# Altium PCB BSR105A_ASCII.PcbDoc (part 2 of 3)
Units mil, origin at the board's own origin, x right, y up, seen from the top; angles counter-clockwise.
Board outline 4010.03 x 4016.63 mil, 6 copper layers (Top Layer, Mid-Layer 1, Mid-Layer 2, Mid-Layer 3, Mid-Layer 4, Bottom Layer), stack 61.2 mil thick; 167 components, 58 nets, 398 pads, 190 vias.
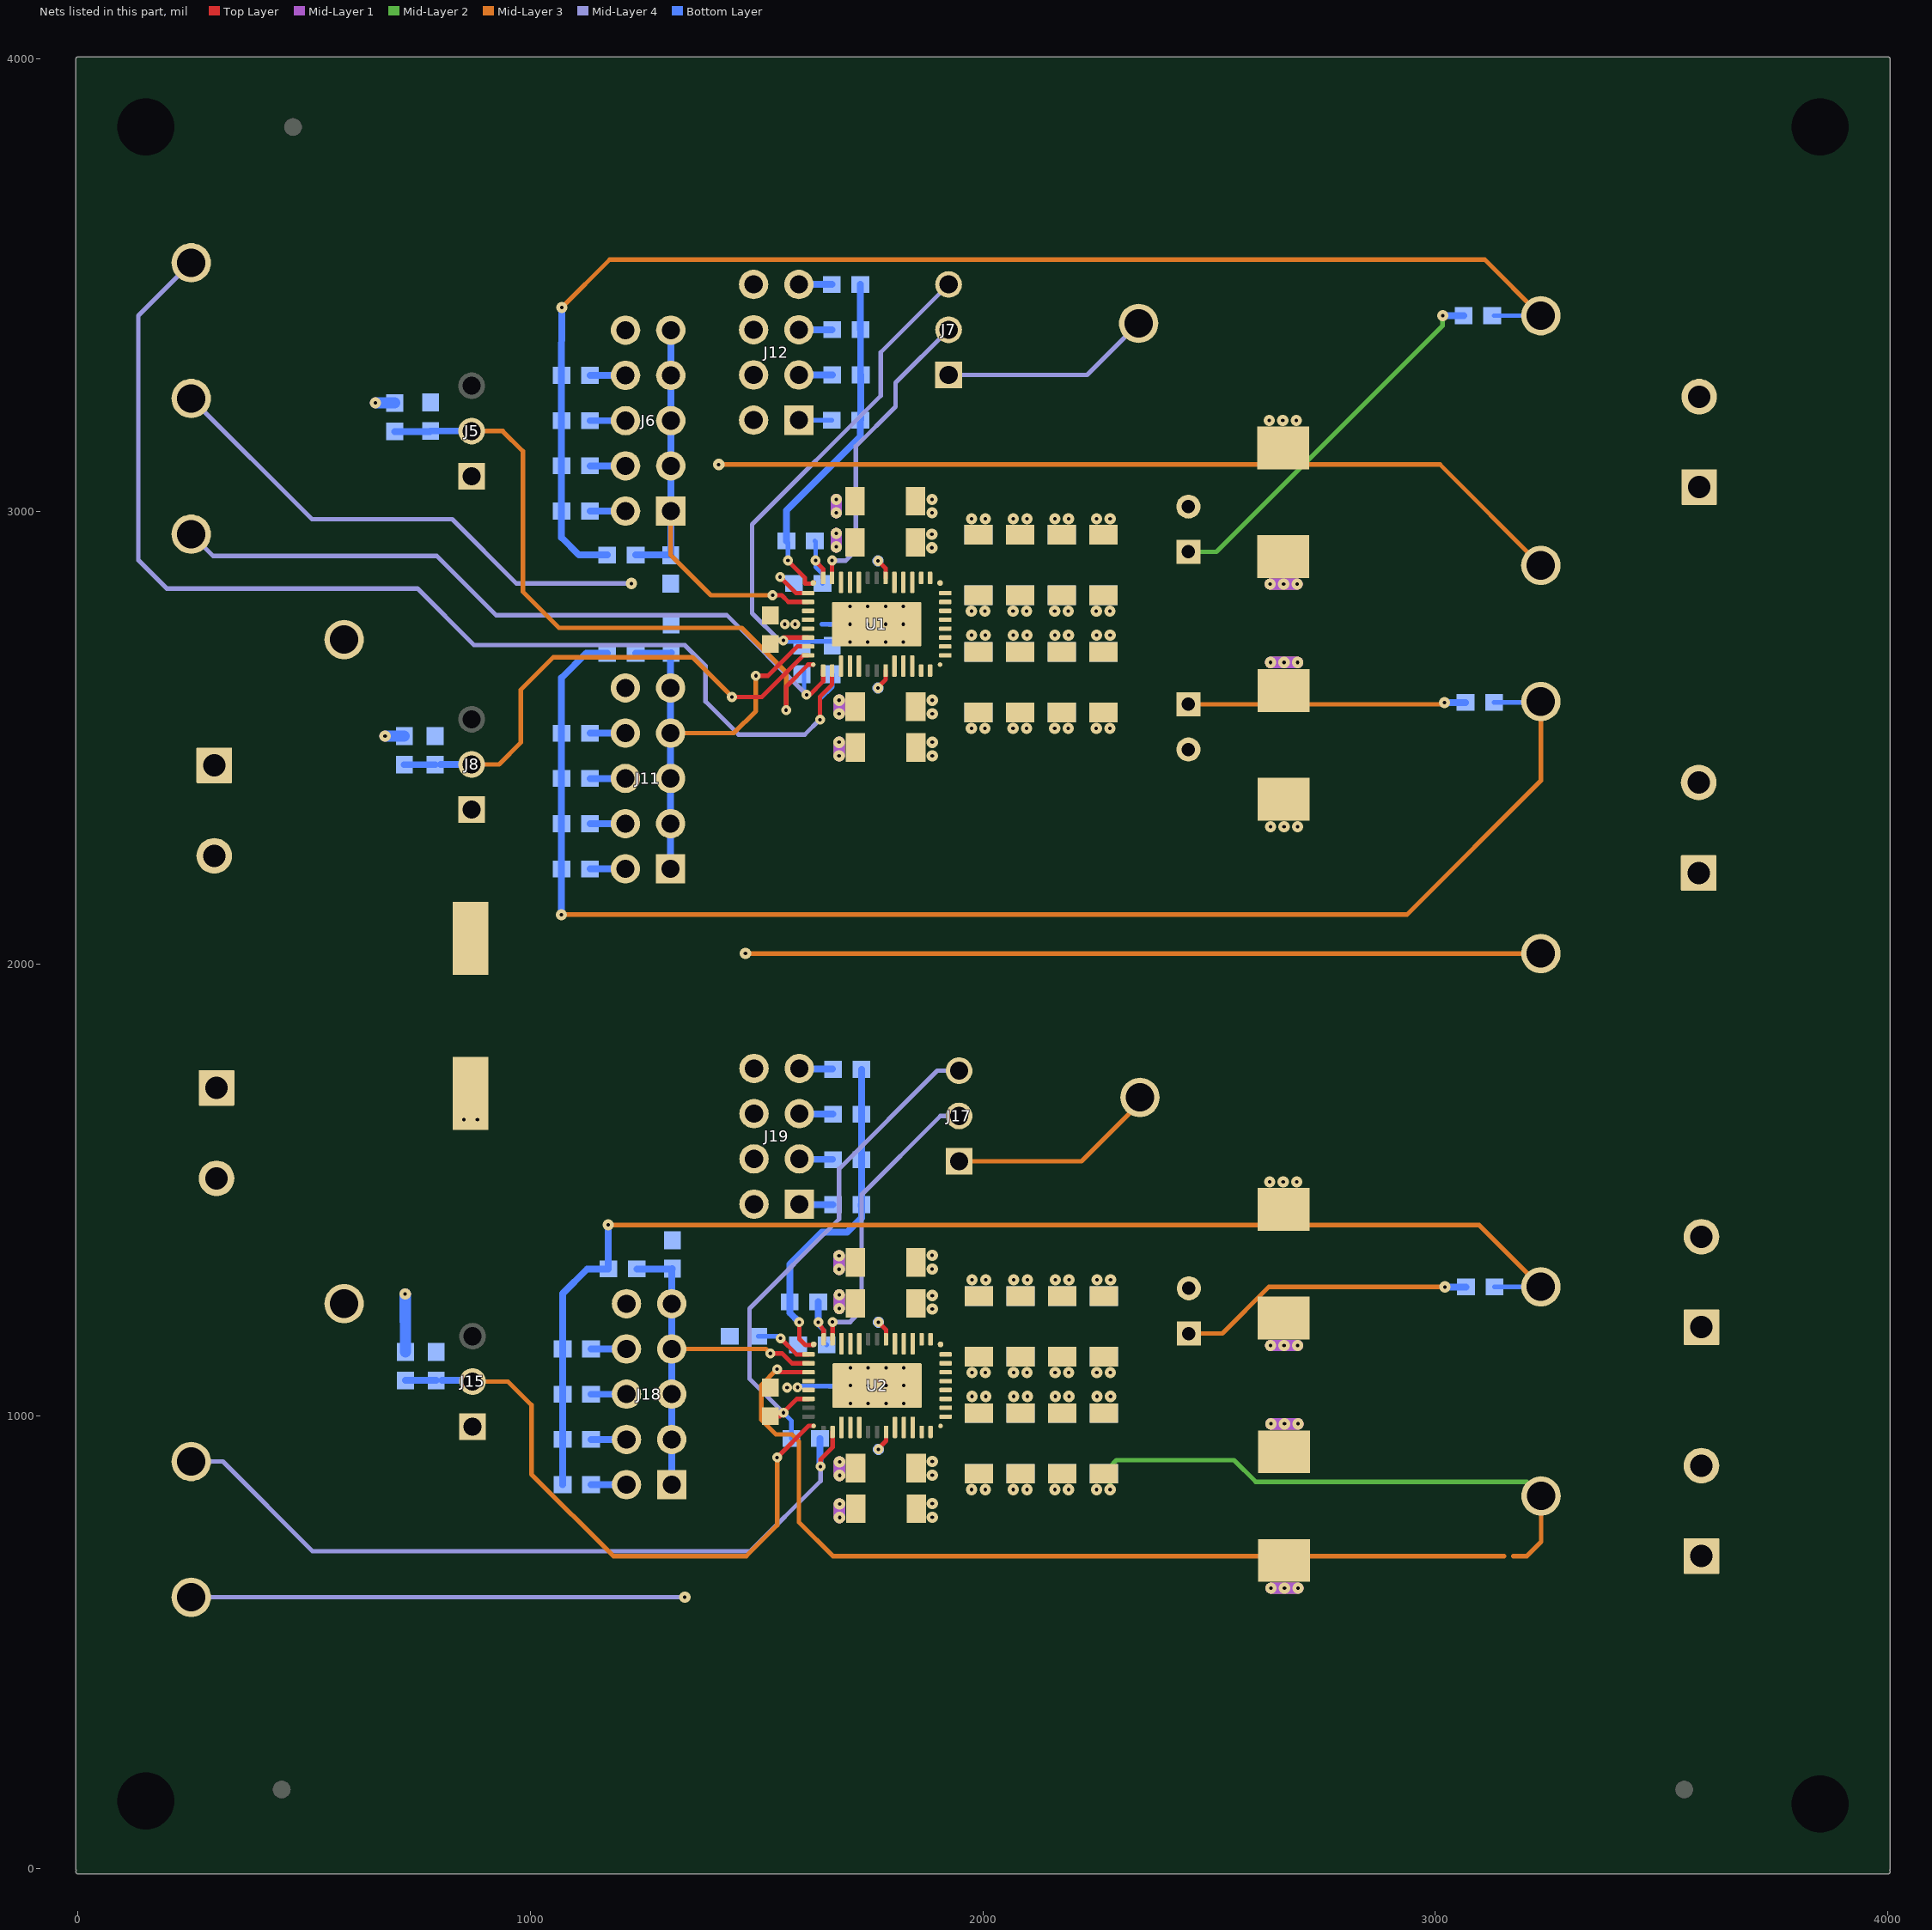
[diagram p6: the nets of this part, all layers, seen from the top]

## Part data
C1: library part CMP-0010657-1, "CAP, AL, 330 uF, 25 V, +/- 20%, 0.15 ohm, SMD"
C2 C3 C4 C5 C25 C26 C27 C28: library part CMP-0008656-2, "CAP, CERM, 47 uF, 25 V, +/- 20%, X5R, 1206_190"
C6 C23 C29 C47: library part CMP-0064986-2, "CAP, Tantalum Polymer, 330 uF, 10 V,+/- 20%, 0.035 ohm, 7343-40 SMD"
C7 C8 C9 C10 C11 C12 C13 C14 C15 C16 C17 C18 C19 C20 C21 C22 C30 C31 C32 C33 C34 C35 C36 C37 C39 C40 C41 C42 C43 C44 C45 C46: library part CMP-0008934-2, "CAP, CERM, 100 uF, 6.3 V, +/- 20%, X5R, 1206"
C24 C48: library part CMP-0007026-4, "CAP, CERM, 2.2 uF, 16 V, +/- 10%, X6S, 0603"
C38: library part CMP-0007049-4, "CAP, CERM, 0.047 uF, 50 V, +/- 10%, X7R, 0603"
FID1 FID2 FID3 FID4 FID5 FID6: library part CMP-0077181-1, "Fiducial mark.  There is nothing to buy or mount."
J1 J3 J4 J10 J13 J16: library part CMP-0074910-1, "Terminal Block, 5.08 mm, 2x1, Brass, TH"
J2 J9 J14: library part CMP-0055017-1, "Socket Strip, 2x1, 100mil, Black, Tin, TH"
J5 J7 J8 J15 J17: library part CMP-0002338-1, "Header, 100mil, 3x1, Tin, TH"
J6 J11 J18: library part CMP-0054550-2, "Header, 100mil, 5x2, Tin, TH"
J12 J19: library part CMP-0054542-2, "Header, 100mil, 4x2, Tin, TH"
Logo1: library part CMP-0074844-1
Logo2: library part CMP-0074838-1, "Texas Instrument Corporate Signature"
Logo3: library part CMP-0074847-1, "FCC_disclaimer"
Logo4: library part CMP-0074769-1
NT1 NT2 NT3: library part CMP-0078142-3, "Single point connection between nets."
R1 R7 R8 R15 R18 R20 R26 R32 R36: library part CMP-0021998-4, "RES, 10.0 k, 1%, 0.1 W, AEC-Q200 Grade 0, 0603"
R2 R13 R27: library part CMP-0025697-4, "RES, 0, 5%, 0.1 W, AEC-Q200 Grade 0, 0603"
R3 R11 R28: library part CMP-0021990-4, "RES, 100 k, 1%, 0.1 W, AEC-Q200 Grade 0, 0603"
R4 R14 R29: library part CMP-0022347-4, "RES, 34.8 k, 1%, 0.1 W, AEC-Q200 Grade 0, 0603"
R5: library part CMP-0022499-4, "RES, 56.2 k, 1%, 0.1 W, AEC-Q200 Grade 0, 0603"
R6: library part CMP-0022563-4, "RES, 6.81 k, 1%, 0.1 W, AEC-Q200 Grade 0, 0603"
R9: library part CMP-0022030-4, "RES, 12.1 k, 1%, 0.1 W, AEC-Q200 Grade 0, 0603"
R10: library part CMP-0022098-4, "RES, 18.7 k, 1%, 0.1 W, AEC-Q200 Grade 0, 0603"
R12: library part CMP-0022443-4, "RES, 48.7 k, 1%, 0.1 W, AEC-Q200 Grade 0, 0603"
R16 R25: library part CMP-0022410-4, "RES, 40.2 k, 1%, 0.1 W, AEC-Q200 Grade 0, 0603"
R17 R22 R37: library part CMP-0022089-4, "RES, 17.4 k, 1%, 0.1 W, AEC-Q200 Grade 0, 0603"
R19 R38: library part CMP-0022261-4, "RES, 28.7 k, 1%, 0.1 W, AEC-Q200 Grade 0, 0603"
R21: library part CMP-0022067-4, "RES, 15.4 k, 1%, 0.1 W, AEC-Q200 Grade 0, 0603"
R23 R40: library part CMP-0022490-4, "RES, 53.6 k, 1%, 0.1 W, AEC-Q200 Grade 0, 0603"
R24: library part CMP-0022213-4, "RES, 21.5 k, 1%, 0.1 W, AEC-Q200 Grade 0, 0603"
R30: library part CMP-0022248-4, "RES, 26.1 k, 1%, 0.1 W, AEC-Q200 Grade 0, 0603"
R31: library part CMP-0022018-4, "RES, 11.5 k, 1%, 0.1 W, AEC-Q200 Grade 0, 0603"
R33: library part CMP-0022079-4, "RES, 16.2 k, 1%, 0.1 W, AEC-Q200 Grade 0, 0603"
R34: library part CMP-0022220-4, "RES, 22.1 k, 1%, 0.1 W, AEC-Q200 Grade 0, 0603"
R35: library part CMP-0022324-4, "RES, 30.1 k, 1%, 0.1 W, AEC-Q200 Grade 0, 0603"
R39 R41 R42: library part CMP-0022001-4, "RES, 10.7 k, 1%, 0.1 W, AEC-Q200 Grade 0, 0603"
SH-J5 SH-J6 SH-J7 SH-J8 SH-J11 SH-J12 SH-J15 SH-J17 SH-J18 SH-J19: library part CMP-0003641-1, "Shunt, 2mm, Gold plated, Black"
TP1 TP2 TP8 TP11: library part CMP-0055147-1, "Test Point, Multipurpose, Red, TH"
TP3 TP6 TP7 TP12 TP14: library part CMP-0055149-1, "Test Point, Multipurpose, White, TH"
TP4 TP5 TP9 TP10 TP13 TP15: library part CMP-0055148-1, "Test Point, Multipurpose, Black, TH"
TP16 TP17 TP18 TP19: library part CMP-0078143-3, "TEST POINT.  No entry in BOM."
U1 U2: library part CMP-0088389-1, "4.5-V to 18-V Input, Dual 6-A Output Power Module with Current Sharing"
ZZ1: library part CMP-0003616-3
ZZ2: library part CMP-0077236-1
ZZ3: library part CMP-0077237-1
ZZ4: library part CMP-0077238-1
ZZ5 ZZ6 ZZ7 ZZ8 ZZ9 ZZ10 ZZ11 ZZ12 ZZ13 ZZ14: library part CMP-0003615-1, "This Assembly Note will show in the PcbDoc and associated outputs"

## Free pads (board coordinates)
  round 120 hole 126 unplated: 2(150,150) 2(150,3850) 2(3850,143.4) 2(3850,3850)

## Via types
v1: diameter 25, hole 7.8, Top Layer to Bottom Layer, 137 vias
v2: diameter 22, hole 7.8, Top Layer to Bottom Layer, 29 vias
v3: diameter 19.68, hole 7.87, Top Layer to Bottom Layer, 24 vias

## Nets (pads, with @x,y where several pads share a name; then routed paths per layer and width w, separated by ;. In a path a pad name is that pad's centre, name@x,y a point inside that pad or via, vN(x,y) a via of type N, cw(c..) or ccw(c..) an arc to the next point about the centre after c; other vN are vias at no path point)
0.8VO1: J6.2 R6.1 | length 78.5
  Bottom Layer w15: R6.1@1131.5,3001 J6.2@1210,3001
0.9VO2: J11.2 R18.1 | length 77.9
  Bottom Layer w15: R18.1@1131.5,2210 J11.2@1209.42,2210
0.9VO3: J18.2 R31.1 | length 77.9
  Bottom Layer w15: R31.1@1133.91,848.83 J18.2@1211.83,848.83
1.0MHz: J12.3 R17.1 | length 74
  Bottom Layer w15: J12.3@1593,3302 R17.1@1667,3302
1.0MHz.: J19.3 R37.1 | length 74.9
  Bottom Layer w10: R37.1@1667.5,1568 R37.1@1668.5,1567
  Bottom Layer w15: J19.3@1594,1568 R37.1@1667.5,1568
1.0VO1: J6.4 R9.1 | length 78.5
  Bottom Layer w15: R9.1@1131.5,3101 J6.4@1210,3101
1.0VO3: J18.4 R33.1 | length 64
  Bottom Layer w15: R33.1@1133.91,948.83 J18.4@1197.17,948.83 ; J18.4@1211.5,949.5 J18.4@1212,949
1.1VO2: J11.4 R22.1 | length 77.9
  Bottom Layer w15: R22.1@1131.5,2310 J11.4@1209.42,2310
1.1VO3: J18.6 R34.1 | length 77.9
  Bottom Layer w15: R34.1@1133.91,1048.83 J18.6@1211.83,1048.83
1.2VO1: J6.6 R10.1 | length 78.5
  Bottom Layer w15: R10.1@1131.5,3201 J6.6@1210,3201
1.2VO2: J11.6 R24.1 | length 77.9
  Bottom Layer w15: R24.1@1131.5,2410 J11.6@1209.42,2410
1.2VO3: J18.8 R35.1 | length 77.9
  Bottom Layer w15: R35.1@1133.91,1148.83 J18.8@1211.83,1148.83
1.5MHz: J12.5 R19.1 | length 73.5
  Bottom Layer w15: J12.5@1593,3402 R19.1@1666.5,3402
1.5MHz.: J19.5 R38.1 | length 74.5
  Bottom Layer w15: J19.5@1594,1668 R38.1@1668.5,1668
1.5VO2: J11.8 R25.1 | length 77.9
  Bottom Layer w15: R25.1@1131.5,2510 J11.8@1209.42,2510
1.8VO1: J6.8 R12.1 | length 77.9
  Bottom Layer w15: R12.1@1131.5,3301 J6.8@1208,3301 ; J6.8@1209,3300 J6.8@1210,3301
1.8VO3: J18.10
2.0MHz: J12.7 R23.1 | length 73
  Bottom Layer w15: J12.7@1593,3502 R23.1@1666,3502
2.0MHz.: J19.7 R40.1 | length 74.9
  Bottom Layer w10: R40.1@1667.5,1768 R40.1@1668.5,1767
  Bottom Layer w15: J19.7@1594,1768 R40.1@1667.5,1768
2.5VO2: J11.10
3.3VO1: J6.10
500kHz: J12.1 R41.1 | length 73
  Bottom Layer w10: J12.1@1593,3202 R41.1@1666,3202
500kHz.: J19.1 R42.1 | length 74.9
  Bottom Layer w15: J19.1@1594,1469 1595,1468 R42.1@1668.5,1468
AGND1: C24.2 J12.2 J12.4 J12.6 J12.8 NT1.1 R8.1 R20.1 R21.1 TP5.1 TP9.1 TP10.1 U1.39 U1.41 U1.42 U1.43 | length 4906.3
  Top Layer w9.8: v2(1551.58,2855.42) 1587.1,2819.9 U1.39@1613.43,2819.9
  Mid-Layer 3 w10: v1(1416,3104) 3010,3104 TP5.1@3233,2881 ; v1(1475,2023) TP9.1@3233,2023
  Mid-Layer 4 w10: TP10.1@250,3250 517,2983 827,2983 969,2841 v1(1223,2841)
  Bottom Layer w10: 1644,2751 NT1.1@1664,2751
  other v2: 1562,2751 1585,2751
AGND2: C38.2 C48.2 J19.2 J19.4 J19.6 J19.8 NT3.1 R32.1 R39.1 TP15.1 U2.42 U2.43 | length 1155.4
  Mid-Layer 4 w10: TP15.1@250,600 v1(1341,600)
  Bottom Layer w10: v2@1599.58,1067 NT3.1@1664,1067
  other v2: 1567,1063.51 1590,1064
BP5-1: C24.1 J7.3 R1.2 R7.2 U1.44 | length 1167.1
  Top Layer w9.8: v2@1555,2717 1559.47,2721.47 U1.44@1613.43,2721.47
  Mid-Layer 4 w10: v2(1558.91,2715.09) 1549.91,2715.09 1489.63,2775.37 1489.63,2971.63 1774,3256 1774,3352 J7.3@1924,3502
  Bottom Layer w9.8: v2(1558.91,2715.09) 1561.07,2712.93 R1.2@1664.07,2712.93
BP5-3: C48.1 J17.3 R26.2 U2.44 | length 1171.4
  Top Layer w10: C48.1@1530,1000.5 1550.93,1000.5 1588.9,1038.47 U2.44@1614.43,1038.47
  Mid-Layer 4 w10: v2(1559,1008) 1484,1083 1484,1238 1682,1436 1682,1547 1899,1764 J17.3@1947,1764
  Bottom Layer w9.8: v2(1559,1008) 1576.5,990.5 R26.2@1576.5,951
EN1: J5.2 R3.1 R4.2 U1.1 | length 1485
  Top Layer w9.8: v2(1565,2561) 1565,2613 1613.73,2661.73 U1.1@1624.74,2661.73
  Mid-Layer 3 w10: J5.2@870,3178 938.44,3178 983,3133.44 983,2823 1063,2743 1467,2743 1565,2645 v2(1565,2561)
  Bottom Layer w15: R3.1@700,3177.09 778,3177.09 R4.2@779,3178.09 J5.2@867.5,3178.09 ; J5.2@867.5,3180.5 J5.2@870,3178
EN2: J8.2 R11.1 R14.2 U1.46 | length 1121.5
  Top Layer w9.8: v2(1445,2590) 1511,2590 1603.1,2682.1 U1.46@1613.43,2682.1
  Mid-Layer 3 w10: J8.2@870,2441 930.19,2441 978.44,2489.25 978.44,2605.83 1050.61,2678 1357.81,2678 1445,2590.81 v2(1445,2590)
  Bottom Layer w15: R11.1@721,2440.5 R14.2@789,2440.5 ; R14.2@801.5,2441 J8.2@870,2441
EN3: J15.2 R28.1 R29.2 U2.1 | length 1346.7
  Top Layer w9.8: v2(1545,909) 1614.73,978.73 U2.1@1625.74,978.73
  Mid-Layer 3 w10: J15.2@872,1077 950,1077 1002,1025 1002,872 1183,691 1476.81,691 1545,759.19 v2(1545,909)
  Bottom Layer w15: R28.1@723.41,1079.33 R29.2@791.41,1079.33 ; R29.2@803.92,1079.83 J15.2@872.41,1079.83
FB1: J6.1 J6.3 J6.5 J6.7 J6.9 R5.1 R8.2 U1.40 | length 1015.2
  Top Layer w9.8: v2(1535,2815) 1555,2815 1569.79,2800.21 U1.40@1613.43,2800.21
  Mid-Layer 3 w10: J6.1@1310,3001 1310,2903.5 1398.5,2815 v2(1535,2815)
  Bottom Layer w15: R5.1@1232.5,2904 R8.2@1309.5,2904 ; R8.2@1310,2906.5 J6.1@1310,3001 J6.3@1310,3101 J6.5@1310,3201 J6.7@1310,3301 J6.9@1310,3401
FB2: J11.1 J11.3 J11.5 J11.7 J11.9 R16.1 R20.2 U1.45 | length 983.5
  Top Layer w9.8: v2(1498,2637) 1525,2637 1589.79,2701.79 U1.45@1613.43,2701.79
  Mid-Layer 3 w10: J11.7@1309.59,2510.17 1449.17,2510.17 1498,2559 v2(1498,2637)
  Bottom Layer w15: R16.1@1232.5,2687 1310.5,2687 R20.2@1311,2687.5 ; J11.1@1309.59,2210.17 J11.3@1309.59,2310.17 J11.5@1309.59,2410.17 J11.7@1309.59,2510.17 J11.9@1309.59,2610.17 R20.2@1309.59,2686.09
FB3: J18.1 J18.3 J18.5 J18.7 J18.9 R30.1 R32.2 U2.40 | length 898.5
  Top Layer w9.8: 1587,1117.21 U2.40@1614.43,1117.21
  Top Layer w10: v2(1530,1139) 1556,1139 1577.79,1117.21 1587,1117.21
  Mid-Layer 3 w10: J18.7@1322,1139 J18.7@1312,1149 1520,1149 v2(1530,1139)
  Mid-Layer 4 w10: J18.7@1312,1149 J18.7@1322,1139
  Bottom Layer w15: R30.1@1234.91,1325.83 1312.91,1325.83 R32.2@1313.41,1326.33 ; J18.1@1312,849 J18.3@1312,949 J18.5@1312,1049 J18.7@1312,1149 J18.9@1312,1249 R32.2@1312,1324.92
MODE1-3: R36.2 R39.2 U2.37 | length 143.9
  Top Layer w9.8: v2(1636,1208) 1647.89,1190.11 U2.37@1647.89,1170.36
  Bottom Layer w10: v2(1636,1208) 1636,1202 1648,1190 1648,1164.5 R39.2@1654.5,1158
  Bottom Layer w15: v2(1636,1208) R36.2@1636,1253
MODE1-U1: R15.2 R21.2 U1.37 | length 146.7
  Top Layer w9.8: U1.37@1646.89,2853.36 1646.89,2873.11
  Top Layer w10: v2(1630,2892) 1630,2890 1646.89,2873.11
  Bottom Layer w10: R15.2@1628.5,2935 1630,2933.5 v2(1630,2892) 1630,2878 1645.5,2862.5 R21.2@1645.5,2841
MODE2-3: R36.1 R37.2 R38.2 R40.2 R42.2 U2.38 | length 746.2
  Top Layer w9.8: v2(1594,1208) 1594,1171 1607.41,1157.59 1624.29,1157.59 U2.38@1625.74,1159.04 U2.38@1627.24,1160.54
  Bottom Layer w15: v2(1594,1208) 1573.01,1228.99 R36.1@1573.01,1253 1573.01,1336.01 1644,1407 1700,1407 1731.5,1438.5 R42.2@1731.5,1468 R37.2@1731.5,1567 R38.2@1731.5,1668 R40.2@1731.5,1767 ; R42.2@1731,1465 R42.2@1731.01,1468
MODE2-U1: R15.1 R17.2 R19.2 R23.2 R41.2 U1.38 | length 767
  Top Layer w9.8: v2@1569,2891 1606.41,2853.59 1606.41,2840.59 1623.29,2840.59 U1.38@1624.74,2842.04 U1.38@1626.24,2843.54
  Bottom Layer w10: R15.1@1565.5,2935 1569,2931.5 v2(1569,2892) ; R41.2@1728.99,3202 R41.2@1729.99,3203 ; R19.2@1728.99,3402.5 R19.2@1729.5,3402 ; R17.2@1729.5,3302.5 R17.2@1729.99,3302
  Bottom Layer w15: R15.1@1565.5,2935 1565.5,3002.5 1728.99,3165.99 R41.2@1728.99,3202 ; R19.2@1728.99,3402.5 R23.2@1728.99,3502 ; R17.2@1729.5,3302.5 R19.2@1729.5,3402 ; R41.2@1729.99,3203 R17.2@1729.99,3302
NetJ7_1: J7.1 TP7.1 | length 467.2
  Mid-Layer 4 w10: J7.1@1924,3302 2230,3302 TP7.1@2344,3416
NetJ17_1: J17.1 TP14.1 | length 465.4
  Mid-Layer 3 w10: J17.1@1947,1564 2218,1564 2347,1693 TP14.1@2347,1705
NetJ17_2: J17.2 U2.36 | length 656.2
  Top Layer w9.8: U2.36@1667.57,1170.36 v2(1667.57,1208.43)
  Mid-Layer 4 w10: v2(1667.57,1208.43) 1706.43,1208.43 1732,1234 1732,1490 1906,1664 J17.2@1947,1664
NetR2_1: R2.1 R5.2 R6.2 R9.2 R10.2 R12.2 TP2.1 | length 2988.2
  Mid-Layer 3 w10: v1(1069,3451) 1175,3557 3109,3557 TP2.1@3233,3433
  Bottom Layer w10: R2.1@3129.5,3433 TP2.1@3233,3433
  Bottom Layer w15: v1(1069,3451) R12.2@1068.5,3301 R10.2@1068.5,3201 R9.2@1068.5,3101 R6.2@1068.5,3001 1068.5,2942.5 1107,2904 R5.2@1169.5,2904
NetR13_1: R13.1 R16.2 R18.2 R22.2 R24.2 R25.2 TP8.1 | length 3513.7
  Mid-Layer 3 w10: v1(1068.5,2109) 2937,2109 3233,2405 TP8.1@3233,2580
  Bottom Layer w10: R13.1@3129.5,2578 TP8.1@3234,2578
  Bottom Layer w15: R18.2@1068.09,2210.17 R25.2@1068.09,2510.17 ; v1(1068.5,2109) R18.2@1068.5,2210 R22.2@1068.5,2310 R24.2@1068.5,2410 R25.2@1068.5,2510 1068.5,2632.5 1123,2687 R16.2@1169.5,2687
NetR27_1: R27.1 R30.2 R31.2 R33.2 R34.2 R35.2 TP11.1 | length 3166.2
  Mid-Layer 3 w10: v1@1171,1423 3096.32,1423 TP11.1@3233,1286.32
  Bottom Layer w10: R27.1@3130.5,1286 TP11.1@3234.68,1286
  Bottom Layer w15: R31.2@1070.5,849 R35.2@1070.5,1149 ; R31.2@1070.92,848.83 R33.2@1070.92,948.83 R34.2@1070.92,1048.83 R35.2@1070.92,1148.83 1070.92,1271.33 1125.41,1325.83 R30.2@1171.92,1325.83 v1(1171.92,1423) ; 1171.81,1403 1171.92,1402.9
PGD1: R1.1 TP3.1 U1.3 | length 2665.3
  Top Layer w9.8: v2(1640,2540) 1640,2590.85 1666.57,2617.43 U1.3@1666.57,2648.64
  Mid-Layer 4 w10: TP3.1@250,3550 133,3433 133,2892.61 195.61,2830 750,2830 875,2705 1341,2705 1386.73,2659.27 1386.73,2580.27 1460,2507 1606,2507 1640,2541 v2(1640,2540)
  Bottom Layer w9.8: v2(1640,2540) 1640,2586 1667,2613 R1.1@1667,2640.5
PGD2: R7.1 TP6.1 U1.2 | length 1636.5
  Top Layer w9.8: v2(1610,2595) 1617.22,2595 1646.89,2624.67 U1.2@1646.89,2648.64
  Mid-Layer 4 w9.8: TP6.1@250,2950 298,2902 793,2902 924,2771 1434,2771 v2(1610,2595)
  Bottom Layer w9.8: R7.1@1604.3,2648.92 1604.3,2601.92 1610,2596.22 v2(1610,2595)
PGD3: R26.1 TP12.1 U2.3 | length 1719.5
  Top Layer w9.8: v2(1641,889) 1641,904.83 1667.57,931.41 U2.3@1667.57,965.64
  Mid-Layer 4 w10: TP12.1@250,900 320,900 518,702 1486,702 1641,857 v2(1641,889)
  Bottom Layer w15: R26.1@1639.5,951 1639.5,890.5 v2(1641,889)
PGND: C1.2 C2.2 C3.2 C4.2 C5.2 C6.2 C7.2 C8.2 C9.2 C10.2 C11.2 C12.2 C13.2 C14.2 C15.2 C16.2 C17.2 C18.2 C19.2 C20.2 C21.2 C22.2 C23.2 C25.2 C26.2 C27.2 C28.2 C29.2 C30.2 C31.2 C32.2 C33.2 C34.2 C35.2 C36.2 C37.2 C39.2 C40.2 C41.2 C42.2 C43.2 C44.2 C45.2 C46.2 C47.2 J2.2 J3.1 J3.2 J4.1 J5.1 J8.1 J9.2 J10.1 J14.2 J15.1 J16.1 J16.2 NT1.2 NT2.2 NT3.2 R4.1 R14.1 R29.1 TP4.1 TP13.1 U1.10 U1.11 U1.12 U1.27 U1.28 U1.29 U1.47-48-49-50-51 U2.10 U2.11 U2.12 U2.27 U2.28 U2.29 U2.47-48-49-50-51 | length 1502.7
  Mid-Layer 1 w25: v1(2636.47,620.41) v1(2666.47,620.41) v1(2696.47,620.41)
  Mid-Layer 2 w10: v1(2281,838) 2281,889 2295,903 2555,903 2603,855 3202.47,855 TP13.1@3233.47,824
  Mid-Layer 3 w10: NT2.2@3172,691 3202,691 3233.47,722.47 TP13.1@3233.47,824
  Mid-Layer 3 w25: v1(2636.47,620.41) v1(2666.47,620.41) v1(2696.47,620.41)
  Mid-Layer 4 w25: v1(2636.47,620.41) v1(2666.47,620.41) v1(2696.47,620.41)
  Bottom Layer w10: NT3.2@1684,1067 v3@1705.94,1067 ; NT1.2@1684,2751 1705.57,2751 v3@1706.36,2751.79
  Bottom Layer w25: v1(2636.47,620.41) v1(2666.47,620.41) v1(2696.47,620.41)
  other v1: 1888,777 1888,807 1975,838 2005,838 2067,838 2097,838 2159,838 2189,838 2251,838 1888,870 1888,900 1888,1237 1888,1267 1976,1302 2006,1302 2068,1302 2098,1302 2160,1302 2190,1302 2252,1302 2282,1302 1887.82,1325.74 1887.82,1355.74 2633.53,1518.41 2663.53,1518.41 2693.53,1518.41 852.51,1656 882.51,1656 2635.47,2303.41 2665.47,2303.41 2695.47,2303.41 1888,2460 1888,2490 1974.49,2521 2004.49,2521 2066.49,2521 2096.49,2521 2158.49,2521 2188.49,2521 2250.49,2521 2280.49,2521 1888,2553 1888,2583 1887,2920 1887,2950 1975,2984 2005,2984 2067,2984 2097,2984 2159,2984 2189,2984 2251,2984 2281,2984 1887.46,2997.04 1887.46,3027.04 2632.53,3201.41 2662.53,3201.41 2692.53,3201.41
  other v3: 1706.94,1028.63 1746.32,1028.63 1785.68,1028.63 1825.06,1028.63 1706.94,1068 1746.32,1068 1785.68,1068 1825.06,1068 1706.94,1107.37 1746.32,1107.37 1785.68,1107.37 1825.06,1107.37 1705.94,2711.63 1745.32,2711.63 1784.68,2711.63 1824.06,2711.63 1705.94,2751 1745.32,2751 1784.68,2751 1824.06,2751 1705.94,2790.37 1745.32,2790.37 1784.68,2790.37 1824.06,2790.37
PVIN: C1.1 C2.1 C3.1 C4.1 C5.1 C25.1 C26.1 C27.1 C28.1 J1.1 J1.2 R3.2 R11.2 R28.2 TP1.1 U1.4 U1.5 U1.6 U1.33 U1.34 U1.35 U2.4 U2.5 U2.6 U2.33 U2.34 U2.35 | length 1173.9
  Mid-Layer 1 w25: v1(1675.54,2921.96) v1(1675.54,2951.96) ; v1(1676,2997) v1(1676,3027) ; v1(1682,1325) v1(1682,1355) ; v1(1682.18,1238.26) v1(1682.18,1268.26) ; v1@1682.35,2460.36 v1@1682.35,2490.36 ; v1@1682.35,2553.36 v1@1682.35,2583.36 ; v1(1683,776.3) v1(1683,806.3) ; v1(1683,869.3) v1(1683,899.3)
  Mid-Layer 3 w25: v1(1675.54,2921.96) v1(1675.54,2951.96) ; v1(1676,2997) v1(1676,3027) ; v1(1682,1325) v1(1682,1355) ; v1(1682.18,1238.26) v1(1682.18,1268.26) ; v1@1682.35,2460.36 v1@1682.35,2490.36 ; v1@1682.35,2553.36 v1@1682.35,2583.36 ; v1(1683,776.3) v1(1683,806.3) ; v1(1683,869.3) v1(1683,899.3)
  Mid-Layer 4 w25: v1(1675.54,2921.96) v1(1675.54,2951.96) ; v1(1676,2997) v1(1676,3027) ; v1(1682,1325) v1(1682,1355) ; v1(1682.18,1238.26) v1(1682.18,1268.26) ; v1@1682.35,2460.36 v1@1682.35,2490.36 ; v1@1682.35,2553.36 v1@1682.35,2583.36 ; v1(1683,776.3) v1(1683,806.3) ; v1(1683,869.3) v1(1683,899.3)
  Bottom Layer w15: R3.2@699.5,3240.59 R3.2@700,3240.09
  Bottom Layer w25: v1(657,3240.59) R3.2@699.5,3240.59 ; v1(678.5,2503.5) R11.2@721,2503.5 ; v1(723,1270.5) R28.2@723.41,1142.32 ; v1(1675.54,2921.96) v1(1675.54,2951.96) ; v1(1676,2997) v1(1676,3027) ; v1(1682,1325) v1(1682,1355) ; v1(1682.18,1238.26) v1(1682.18,1268.26) ; v1@1682.35,2460.36 v1@1682.35,2490.36 ; v1@1682.35,2553.36 v1@1682.35,2583.36 ; v1(1683,776.3) v1(1683,806.3) ; v1(1683,869.3) v1(1683,899.3)
  other v1: 1682,2460 1682,2490 1682,2553 1682,2583
RS-3: NT2.1 U2.41 | length 2069.7
  Top Layer w9.8: v2(1545,1104) 1551.47,1097.53 U2.41@1614.43,1097.53
  Mid-Layer 3 w10: v2(1545,1104) 1510,1069 1510,992.19 1542.36,959.83 1577.54,959.83 1593.1,944.27 1593.1,765.9 1668,691 NT2.1@3152,691
SS3: C38.1 U2.39 | length 121.1
  Top Layer w9.8: v2(1552.58,1172.42) 1588.1,1136.9 U2.39@1614.43,1136.9
  Bottom Layer w10: C38.1@1503.5,1177 v2@1548,1177
SW1: TP16.1 U1.30 | length 44.5
  Top Layer w9.8: v2(1768,2891) 1784.68,2874.31 U1.30@1784.68,2853.36
SW2: TP17.1 U1.9 | length 43.5
  Top Layer w9.8: v2@1768,2612 1784.68,2628.69 U1.9@1784.68,2648.64
  other v2: 1768,2610
SW3-1: TP18.1 U2.30 | length 44.5
  Top Layer w9.8: v2(1769,1208) 1785.68,1191.32 U2.30@1785.68,1170.36
SW3-2: TP19.1 U2.9 | length 43.5
  Top Layer w9.8: v2@1769,929 1785.68,945.68 U2.9@1785.68,965.64
  other v2: 1769,927
SYNC: J7.2 U1.36 | length 672.8
  Top Layer w9.8: U1.36@1666.57,2853.36 v2@1666.57,2891.43
  Mid-Layer 4 w10: v2@1666.57,2891.43 1696.43,2891.43 1719,2914 1719,3144 1807,3232 1807,3285 J7.2@1924,3402
  other v2: 1666.57,2892
VOUT1: C6.1 C7.1 C8.1 C9.1 C10.1 C11.1 C12.1 C13.1 C14.1 J2.1 J4.2 R2.2 U1.20 U1.21 U1.22 U1.23 U1.24 U1.25 U1.26 | length 1077.6
  Mid-Layer 1 w25: v1(2634.47,2839.41) v1(2664.47,2839.41) v1(2694.47,2839.41)
  Mid-Layer 2 w10: J2.1@2454,2911 2516,2911 3016,3411 v1(3016,3433)
  Mid-Layer 3 w25: v1(2634.47,2839.41) v1(2664.47,2839.41) v1(2694.47,2839.41)
  Mid-Layer 4 w25: v1(2634.47,2839.41) v1(2664.47,2839.41) v1(2694.47,2839.41)
  Bottom Layer w15: v1(3016,3433) R2.2@3062.5,3433
  Bottom Layer w25: v1(2634.47,2839.41) v1(2664.47,2839.41) v1(2694.47,2839.41)
  other v1: 1974.49,2779.84 2004.49,2779.84 2066.49,2779.84 2096.49,2779.84 2158.49,2779.84 2188.49,2779.84 2250.49,2779.84 2280.49,2779.84
VOUT2: C15.1 C16.1 C17.1 C18.1 C19.1 C20.1 C21.1 C22.1 C23.1 J9.1 J10.2 R13.2 U1.13 U1.14 U1.15 U1.16 U1.17 U1.18 U1.19 | length 868.3
  Mid-Layer 1 w25: v1(2635.5,2666.41) v1(2665.5,2666.41) v1(2695.5,2666.41)
  Mid-Layer 3 w10: J9.1@2454,2574 3016,2574 v1(3020,2578) ; J10.2@3572,2411 J10.2@3582,2401
  Mid-Layer 3 w25: v1(2635.5,2666.41) v1(2665.5,2666.41) v1(2695.5,2666.41)
  Mid-Layer 4 w25: v1(2635.5,2666.41) v1(2665.5,2666.41) v1(2695.5,2666.41)
  Bottom Layer w15: v1(3020,2578) R13.2@3066.5,2578
  Bottom Layer w25: v1(2635.5,2666.41) v1(2665.5,2666.41) v1(2695.5,2666.41)
  other v1: 1975,2727 2005,2727 2067,2727 2097,2727 2159,2727 2189,2727 2251,2727 2281,2727
VOUT3: C29.1 C30.1 C31.1 C32.1 C33.1 C34.1 C35.1 C36.1 C37.1 C39.1 C40.1 C41.1 C42.1 C43.1 C44.1 C45.1 C46.1 C47.1 J13.1 J13.2 J14.1 R27.2 U2.13 U2.14 U2.15 U2.16 U2.17 U2.18 U2.19 U2.20 U2.21 U2.22 U2.23 U2.24 U2.25 U2.26 | length 1139.4
  Mid-Layer 1 w25: v1(2635.47,1156.41) v1(2665.47,1156.41) v1(2695.47,1156.41) ; v1(2636.5,983.41) v1(2666.5,983.41) v1(2696.5,983.41)
  Mid-Layer 3 w10: J14.1@2455,1183 2529,1183 2632,1286 v1(3021,1286) ; J13.2@3585,1400 J13.2@3588,1397
  Mid-Layer 3 w25: v1(2635.47,1156.41) v1(2665.47,1156.41) v1(2695.47,1156.41) ; v1(2636.5,983.41) v1(2666.5,983.41) v1(2696.5,983.41)
  Mid-Layer 4 w25: v1(2635.47,1156.41) v1(2665.47,1156.41) v1(2695.47,1156.41) ; v1(2636.5,983.41) v1(2666.5,983.41) v1(2696.5,983.41)
  Bottom Layer w15: v1(3021,1286) R27.2@3067.5,1286
  Bottom Layer w25: v1(2635.47,1156.41) v1(2665.47,1156.41) v1(2695.47,1156.41) ; v1(2636.5,983.41) v1(2666.5,983.41) v1(2696.5,983.41)
  other v1: 1976,1044 2006,1044 2068,1044 2098,1044 2160,1044 2190,1044 2252,1044 2282,1044 1975.49,1096.84 2005.49,1096.84 2067.49,1096.84 2097.49,1096.84 2159.49,1096.84 2189.49,1096.84 2251.49,1096.84 2281.49,1096.84
pads on no net: FID1.1 FID2.1 FID3.1 FID4.1 FID5.1 FID6.1 J5.3 J8.3 J15.3 SH-J5.0 SH-J6.0 SH-J7.0 SH-J8.0 SH-J11.0 SH-J12.0 SH-J15.0 SH-J17.0 SH-J18.0 SH-J19.0 U1.7 U1.8 U1.31 U1.32 U2.2 U2.7 U2.8 U2.31 U2.32 U2.45 U2.46
copper on no net:
  other v1: 1447.41,848.83 671,1549
  other v2: 1473.59,762.17

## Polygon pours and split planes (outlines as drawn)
PGND on Top Layer "TOP_LAYER_PGND_P121" (solid, remove dead copper, pour order 121): 1797.58,1146.76 1636.58,1146.76 1636.58,986.76 1638.58,988.76 1797.58,988.76
PGND on Top Layer "TOP_LAYER_PGND_P118" (solid, remove dead copper, pour order 118): 1798.1,2831 1637.1,2831 1637.1,2671 1639.1,2673 1798.1,2673
AGND1 on Top Layer "TOP_LAYER_AGND1_P117" (solid, remove dead copper, pour order 117): 1628,2736 1557,2736 1542,2751 1513,2751 1513,2786 1513,2790 1553,2790 1557,2786 1628,2786
VOUT3 on Top Layer "TOP_LAYER_VOUT3_P122" (solid, remove dead copper, pour order 122): 1896.35,1220.17 2515.2,1220.2 2567.67,1272.67 3146,1273 3467,1594 3635,1594 3685,1544 3685,1120.41 3429.59,865 2613,865 2560,918 1860,918 1860,1009 1874,1009 1874,1059 1874,1126.43 1860,1126.43 1860,1183.81
VOUT2 on Top Layer "TOP_LAYER_VOUT2_P124" (solid, remove dead copper, pour order 124): 1860.89,2746.89 3499,2746.63 3499,2706.01 3539.01,2666 3656,2666 3691,2631 3691,2327 3667,2303 3009,2303 2782,2530 2422,2530 2344,2608 1857,2608 1857,2693 1857,2743
VOUT1 on Top Layer "TOP_LAYER_VOUT1_P128" (solid, remove dead copper, pour order 128): 1860.49,2756.51 3440,2756.76 3498,2756.77 3498,3109.52 3537.48,3149 3609,3149 3663,3149 3688,3174 3688,3494 3647,3535 3300,3535 2726,2961 2396,2961 2352.28,2917.28 1918.28,2917.28 1893,2892 1883.22,2892 1857,2865.78 1857,2810.43 1857,2760
BP5-3 on Top Layer "TOP_LAYER_BP5-3_P116" (solid, remove dead copper, pour order 116): 1627,1044 1584.83,1044 1582.74,1044 1558.15,1019.42 1511.89,1019.42 1511.89,981 1548,981 1600,1033 1627,1033
AGND2 on Top Layer "TOP_LAYER_AGND2_P112" (solid, remove dead copper, pour order 112): 1572,1045 1512.2,1045 1512.2,1082.95 1562.52,1082.95 1595,1082.95 1629,1082.95 1629,1053.32 1580.32,1053.32
FB3 on Top Layer "TOP_LAYER_FB3_P119" (solid, remove dead copper, pour order 119): 1627,1122 1581,1122 1553.04,1149.96 1519.28,1149.96 1519.28,1133.69 1541.38,1111.59 1627,1111.59
BP5-1 on Top Layer "TOP_LAYER_BP5-1_P115" (solid, remove dead copper, pour order 115): 1626,2727 1511,2727 1511,2688 1571,2688 1599,2716 1626,2716
PVIN on Top Layer "TOP_LAYER_PVIN_P123" (solid, remove dead copper, pour order 123): 184,2010 184,2793 819,3428 1590,3428 1744,3274 1744,514 1712,482 1017,482 962,537 962,1232 825,1369 683,1511
PGND on Top Layer "TOP_LAYER_PGND_P132" (solid, remove dead copper, pour order 132): 2,-8 0,-6 0,4000 4000,4000 4000,-2.67
VOUT3 on Mid-Layer 2 "MID-LAYER_2_VOUT3_P138" (solid, remove dead copper, pour order 138): 2038.18,1219.14 2518.16,1219.16 2561.8,1262.8 3140.13,1263.13 3399,1522 3739,1522 3778,1483 3778,1272 3778,1171 3471,864 2616,864 2563,917 1956.82,917 1956.82,1219.15
VOUT2 on Mid-Layer 2 "MID-LAYER_2_VOUT2_P148" (solid, remove dead copper, pour order 148): 1960,2745.87 3536,2745.63 3536,2692 3563,2665 3637,2665 3758,2544 3758,2519.99 3758,2336 3724,2302 2810,2302 2565,2547 2505,2607 1960,2607
VOUT1 on Mid-Layer 2 "MID-LAYER_2_VOUT1_P146" (solid, remove dead copper, pour order 146): 1958.82,2755.53 3443,2755.76 3534.23,2755.77 3534.23,3110.23 3572,3148 3612,3148 3742,3148 3797,3203 3797,3445 3708,3534 3162,3534 2532,2904 1958.82,2904
PVIN on Mid-Layer 2 "MID-LAYER_2_PVIN_P140" (solid, remove dead copper, pour order 140): 187,2073 187,2807 691,3311 1709,3311 1747,3273 1747,2899 1747,2825 1696.98,2825 1649,2777.02 1649,2719 1690,2678 1747,2678 1747,2621 1747,1147 1686,1147 1649,1110 1649,1074 1649,1035 1691,993 1747,993 1747,513 1715,481 1020,481 965,536 965,1231 733,1231 703,1261 703,1557
PGND on Mid-Layer 2 "MID-LAYER_2_PGND_P150" (solid, remove dead copper, pour order 150): 3,347.14 3,3999 4003,3999 4003,352.47 4003,-14.61 4.53,-11.61
BP5-1 on Bottom Layer "BOTTOM_LAYER_BP5-1_P154" (solid, remove dead copper, pour order 154): 1681,2728 1686.26,2722.74 1686.26,2682.1 1627.9,2682.1 1560.87,2682.1 1544,2698.97 1544,2722 1550,2728
AGND2 on Bottom Layer "AGND2" (solid, pour order 160): 926,1785 1684.02,1785 1684.02,480 926,480
AGND1 on Bottom Layer "Bottom Layer-AGND1" (solid, pour order 158): 943,3494 1679.19,3494 1679.19,1987 943,1987
PGND on Bottom Layer "Bottom Layer-No Net" (solid, pour order 162): 8.54,-7 8.54,3993 4008.54,3993 4008.54,-7
PGND on Mid-Layer 3 "MID-LAYER_3_PGND_P136" (solid, remove dead copper, pour order 136): 4,2 4,4002 4000,4002 4000,2
PGND on Mid-Layer 4 "MID-LAYER_4_PGND_P152" (solid, remove dead copper, pour order 152): 0,-11.61 0,4000 4000,4000 4000,-11.61
PGND on Mid-Layer 1 "MID-LAYER_1_PGND_P134" (solid, remove dead copper, pour order 134): 0,0 0,4000 4000,4000 4000,0

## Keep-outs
Keep-Out Layer:
  text ".Layer_Name" at 577,-858.49 h60

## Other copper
Top Layer:
  text "COMPONENT SIDE METAL" at 1196,-202 h100
  text ".Layer_Name" at 577,-858.49 h60
Mid-Layer 1:
  rectangle net VOUT3: 1959.63,1028.5 2297.5,1111.8
  text "LAYER 2 METAL" at 1502,-202 h100
Mid-Layer 2:
  text "LAYER 3 METAL" at 1502,-202 h100
Mid-Layer 3:
  rectangle net VOUT3: 1959.63,1028.5 2297.5,1111.8
  text "LAYER 4 METAL" at 1502,-203 h100
Mid-Layer 4:
  text "LAYER 5 METAL" at 1451,-202 h100
Bottom Layer:
  rectangle net VOUT1: 1958.45,2767 2298,2837
  rectangle net VOUT2: 1958.45,2668 2298,2740
  rectangle net VOUT3: 1959.45,984 2299,1154
  text "SOLDER SIDE METAL" at 1315,-202 h100
  text ".Layer_Name" at 577,-858.49 h60

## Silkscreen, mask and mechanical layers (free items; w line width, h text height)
Top Overlay:
  lines w7: 1990,3284 2012,3284 2012,3387 1990,3387 ; 1990,3407 2012,3407 ; 1990,3510 2012,3510 2012,3407 ; 2000,3407 2012,3407 ; 2012,1552 2034,1552 ; 2012,1655 2034,1655 2034,1552 ; 2012,1675 2034,1675 ; 2012,1778 2034,1778 2034,1675 ; 2016,3334 2048,3334 ; 2016,3457 2048,3457 ; 2022,1552 2034,1552 ; 2022,1675 2034,1675 ; 2038,1602 2070,1602 ; 2038,1725 2070,1725
  lines w8: 1430,574 2388,574 ; 1501,2260 2287,2260
  text "'.PRJ_Title'" at 1510,3810 h150
  text "SYNC" at 2155,3570 h50
  text "PGOOD1" at 360,3524 h50
  text "1&2" at 2157,3496 h50
  text "Fsw(Hz)" at 1365,3491 h50
  text "VOUT1" at 1109,3480.41 h50
  text "2.0M" at 1595,3480 h50
  text "VOUT1" at 2939,3451 h50
  text "Fsw" at 1981,3429 h50
  text "VOUT1" at 3462,3386 h50
  text "S+" at 3005,3371 h50
  text "1.5M" at 1593,3370 h50
  text "3.3V" at 987,3368 h50
  text "EN1" at 809,3344 h50
  text "SYNC" at 2000,3292 h50
  text "1.0M" at 1592,3270 h50
  text "1.8V" at 989,3268 h50
  text "AGND" at 364,3227 h50
  text "ON" at 690,3218 h50
  text "500k" at 1593,3170 h50
  text "1.2V" at 993,3168 h50
  text "MAX / 6A" at 3790,3089 h50
  text "OFF" at 673,3084 h50
  text "1.0V" at 989,3068 h50
  text "0.8V" at 987,2968 h50
  text "PGOOD2" at 357,2924 h50
  text "VOUT1" at 2925,2884 h50
  text "PGND" at 3496,2880 h50
  text "+" at 2784,2878 h50
  text "+" at 2339,2860 h50
  text "S-" at 2999,2811 h50
  text "VOUT1" at 2360,2755 h50
  text "VIN" at 394,2718 h50
  text "VOUT2" at 1112,2685.33 h50
  text "VOUT2" at 2361,2666 h50
  text "S+" at 401,2650 h50
  text "+" at 2351,2620 h50
  text "EN2" at 798,2604 h50
  text "VOUT2" at 2922,2593 h50
  text "+" at 2790,2581 h50
  text "2.5V" at 985,2577 h50
  text "VIN" at 230,2560 h50
  text "VOUT2" at 3457,2534 h50
  text "S+" at 3001,2512 h50
  text "ON" at 690,2481 h50
  text "1.5V" at 988.59,2477.17 h50
  text "1.2V" at 992,2378 h50
  text "OFF" at 678.8,2361 h50
  text "1.1V" at 991,2277 h50
  text "MAX / 6A" at 3789,2236 h50
  text "U1: DUAL 6A OUTPUTS" at 1446,2209 h50
  text "0.9V" at 989.59,2177.17 h50
  text "VOUT2" at 2922,2046 h50
  text "PGND" at 3495,2027 h50
  text "S-" at 3001,1969 h50
  text "SYNC 3" at 2206,1798 h50
  text "Fsw(Hz)" at 1354,1755 h50
  text "2.0M" at 1590,1734 h50
  text "Fsw" at 2003,1691 h50
  text "1.5M" at 1585,1638 h50
  text "SYNC" at 2027,1571 h50
  text "1.0M" at 1590,1539 h50
  text "VOUT3" at 3454,1536 h50
  text "500k" at 1598,1431 h50
  text "PGND" at 226,1342 h50
  text "VOUT3" at 1115,1322 h50
  text "VOUT3" at 2920,1299.32 h50
  text "VIN" at 396,1254 h50
  text "EN3" at 800,1240 h50
  text "S+" at 2997,1222 h50
  text "1.8V" at 990.59,1213.17 h50
  text "+" at 2785,1195 h50
  text "S-" at 408,1186 h50
  text "+" at 2340,1132 h50
  text "1.2V" at 990.59,1113.17 h50
  text "ON" at 689,1099 h50
  text "VOUT3" at 2352,1035 h50
  text "1.1V" at 997,1013 h50
  text "MAX / 12A" at 3796,976 h50
  text "OFF" at 675,972.5 h50
  text "1.0V" at 990.59,913.17 h50
  text "+" at 2791,898 h50
  text "PGOOD3" at 350,874 h50
  text "VOUT3" at 2919.47,836 h50
  text "0.9V" at 991.59,813.17 h50
  text "S-" at 2998.47,759 h50
  text "U2: PARALLEL 12A OUTPUT" at 1405,590 h50
  text "AGND" at 355,573 h50
  text "PGND" at 3492,499 h50
  text "'.PRJ_Number'.PCB_Rev" at 3036,52 h50
  text "COMPONENT SIDE SILK SCREEN" at 992,-202 h100
  text ".Layer_Name" at 577,-858.49 h40
Bottom Overlay:
  text "SOLDER SIDE SILK SCREEN" at 1103,-202 h100
  text ".Layer_Name" at 577,-858.49 h60
Top Paste:
  text "COMPONENT SIDE PASTE" at 1169,-202 h100
  text ".Layer_Name" at 577,-858.49 h60
Bottom Paste:
  text "SOLDER SIDE PASTE" at 1237,-202 h100
  text ".Layer_Name" at 577,-858.49 h60
Top Solder:
  text "COMPONENT SIDE SOLDER MASK" at 802,-202 h100
  text ".Layer_Name" at 577,-858.49 h60
  text ".Layer_Name" at 577,-858.49 h60
Bottom Solder:
  text "SOLDER SIDE SOLDER MASK" at 955,-202 h100
  text ".Layer_Name" at 577,-858.49 h60
Drill Guide:
  text ".Layer_Name" at 577,-858.49 h60
M1 Board Outline:
  lines w10: 0,-6.6 4000,-6.6 ; 0,0 0,4000 4000,4000 4000,0
  text ".Layer_Name" at 577,-858.49 h60
M2 Board Dimensions:
  rectangle: 0,-292 125,-167
  rectangle: 125,-417 500,-292
  lines w7: 0,-292 1000,-292 ; 125,-417 125,-167 ; 250,-417 250,-167 ; 500,-417 500,-167 ; 750,-417 750,-167 ; 0,-417 1000,-417 1000,-167 0,-167 0,-417
  text ".Layer_Name" at 577,-858.49 h60
M3 3D STEP Top:
  text ".Layer_Name" at 577,-858.49 h60
M4 3D STEP Bottom:
  text ".Layer_Name" at 577,-858.49 h60
M5 Assembly Top:
  lines w10: -292,-930.17 6308,-930.17 ; -292,-726.83 6310,-726.83 ; -292,-523.5 -292,-1133.5 3713,-1133.5 6310,-1133.5 6310,-523.5 -291.5,-523.5 -291.5,-1133.5 1284,-1133.5 ; 2173,-1133.5 2173,-523.5 ; 3440,-726.83 3440,-523.5 ; 4280,-726.83 4280,-523.5 ; 4902,-1140 4902,-937.17
  text "COMPONENTS MARKED 'DNP' SHOULD NOT BE POPULATED." at 1153.5,-318.5 h60
  text "ASSEMBLY VARIANT:" at 1153,-434 h60
  text ".VariantName" at 2189,-434 h60
  text "PCB VIEWED FROM TOP SIDE" at -228.5,-655.67 h60
  text "BOARD #:" at 2248,-655.67 h60
  text ".PRJ_Number" at 2793.5,-655.67 h60
  text "REV:" at 3638,-655.67 h60
  text ".PCB_Rev" at 3929.5,-655.67 h60
  text "SVN REV:" at 4476,-655.67 h60
  text ".VersionControl_RevNumber" at 4982,-655.67 h60
  text "TID #:" at 2248,-859 h60
  text ".TID" at 2793.5,-859 h60
  text "PLOT NAME =" at -228.5,-1064.34 h60
  text ".plot_File_Name" at 577,-1064.34 h60
  text "GENERATED    :" at 2250,-1064.34 h60
  text ".Print_Date" at 3119.5,-1064.34 h60
  text ".Print_Time" at 3848.5,-1064.34 h60
  text "TEXAS INSTRUMENTS" at 5113,-1064.34 h60
M6 Assembly Bottom:
  lines w10: -292.5,-727.33 6309.5,-727.33 ; -290.5,-930.67 6309.5,-930.67 ; 1115.5,-1140.5 1115.5,-937.67 ; 1737.5,-727.33 1737.5,-524 ; 2577.5,-727.33 2577.5,-524 ; 3844.5,-1134 3844.5,-524 ; 4733.5,-1134 6309,-1134 6309,-524 -292.5,-524 -292.5,-1134 2304.5,-1134 6309.5,-1134 6309.5,-524
  text "COMPONENTS MARKED 'DNP' SHOULD NOT BE POPULATED." at 6102,-318 h60
  text ".VariantName" at 5058,-434 h60
  text "ASSEMBLY VARIANT:" at 6097,-434 h60
  text ".VersionControl_RevNumber" at 1035.5,-656.17 h60
  text "SVN REV:" at 1541.5,-656.17 h60
  text ".PCB_Rev" at 2088,-656.17 h60
  text "REV:" at 2379.5,-656.17 h60
  text ".PRJ_Number" at 3224,-656.17 h60
  text "BOARD #:" at 3769.5,-656.17 h60
  text "PCB VIEWED FROM BOTTOM SIDE" at 6246,-656.17 h60
  text ".TID" at 3224,-859.5 h60
  text "TID #:" at 3769.5,-859.5 h60
  text "TEXAS INSTRUMENTS" at 904.5,-1064.84 h60
  text ".Print_Time" at 2169,-1064.84 h60
  text ".Print_Date" at 2898,-1064.84 h60
  text "GENERATED    :" at 3767.5,-1064.84 h60
  text ".plot_File_Name" at 5440.5,-1064.84 h60
  text "PLOT NAME =" at 6246,-1064.84 h60
M9 Title Sheet:
  lines w10: -491.5,1041.5 -291.5,1041.5 ; -491.5,3416.5 -291.5,3416.5 ; -491.5,5791.5 -291.5,5791.5 ; 2008.5,-1333.5 2008.5,-1133.5 ; 2008.5,7966.5 2008.5,8166.5 ; 4508.5,-1333.5 4508.5,-1133.5 ; 4508.5,7966.5 4508.5,8166.5 ; 6321,-1133.5 6321,-523.5 11303.5,-523.5 ; 7008.5,-1333.5 7008.5,-1133.5 ; 7008.5,7966.5 7008.5,8166.5 ; 9508.5,-1333.5 9508.5,-1133.5 ; 9508.5,7966.5 9508.5,8166.5 ; 11303.5,-1133.5 11303.5,-523.5 ; 11303.5,-823.5 14303.5,-823.5 ; 11303.5,-223.5 14303.5,-223.5 ; 11304.5,370.5 14304.5,370.5 ; 12008.5,-1333.5 12008.5,-1133.5 ; 12008.5,7966.5 12008.5,8166.5 ; 12808.5,-1123.5 12808.5,-523.5 ; 14303.5,-523.5 11303.5,-523.5 ; 14303.5,76.5 11303.5,76.5 ; 14308.5,66.5 14308.5,-1133.5 ; 14308.5,871 11304.5,871 11303.5,871 11303.5,370.5 11303.5,76.5 ; 14308.5,1041.5 14508.5,1041.5 ; 14308.5,3416.5 14508.5,3416.5 ; 14308.5,5791.5 14508.5,5791.5 ; 11303.5,-523.5 11303.5,76.5 ; 14308.5,-1133.5 14308.5,7966.5 -291.5,7966.5 -291.5,-1133.5 14308.5,-1133.5 ; -491.5,-1333.5 -491.5,8166.5 14508.5,8166.5 14508.5,-1333.5 -491.5,-1333.5
  text "1" at 739.84,8036.5 h70
  text "2" at 3235.5,8036.5 h70
  text "3" at 5724.84,8036.5 h70
  text "4" at 8231.51,8036.5 h70
  text "5" at 10730.5,8036.5 h70
  text "6" at 13235.5,8036.5 h70
  text "A" at -416.5,6893.5 h70
  text "A" at 14383.5,6893.5 h70
  text "B" at -416.5,4513.5 h70
  text "B" at 14383.5,4513.5 h70
  text "C" at -416.5,2138.5 h70
  text "C" at 14383.5,2138.5 h70
  text "PROJECT TITLE:" at 11343.5,277.5 h45
  text ".PRJ_Title" at 11393.5,144.17 h70
  text "DESIGNED FOR:" at 11343.5,-23.5 h45
  text ".PRJ_Customer" at 11393.5,-163.5 h70
  text "D" at -416.5,-231.5 h70
  text "D" at 14383.5,-231.5 h70
  text "FILE NAME:" at 11343.5,-323.5 h45
  text ".PCB_File_Name_No_Path" at 11393.5,-443.5 h70
  text "Texas Instruments (TI) and/or its licensors do not warrant the accuracy or completeness of this specification" at 6374,-605.34 h45
  text "ENGINEER:" at 11343.5,-613.5 h45
  text "LAYOUT BY:" at 12848.5,-613.5 h45
  text "or any information contained therein. TI and/or its licensors do not warrant that this design will meet" at 6329.01,-718 h45
  text ".PRJ_Engineer" at 11393.5,-768.49 h70
  text ".PCB_Layout" at 12899,-768.49 h70
  text "the specifications, will be suitable for your application or fit for any particular purpose, or will operate in" at 6329.01,-830.67 h45
  text ".Layer_Name" at 577,-858.49 h60
  text "ALTIUM DESIGNER VERSION:" at 12848.5,-923.5 h45
  text "an implementation. TI and/or its licensors do not warrant that the design is production worthy. You should" at 6329.01,-943.33 h45
  text "completely validate and test your design implementation to confirm the system functionality for your application." at 6374,-1056 h45
  text ".print_Scale" at 11393.5,-1056.83 h70
  text ".Application_BuildNumber" at 12899,-1056.83 h70
  text "1" at 739.84,-1263.5 h70
  text "2" at 3235.5,-1263.5 h70
  text "3" at 5724.84,-1263.5 h70
  text "4" at 8231.51,-1263.5 h70
  text "5" at 10730.5,-1263.5 h70
  text "6" at 13235.5,-1263.5 h70
M10 Fab Notes:
  drawing of 189 lines, arcs and shapes, not listed
  text "DESIGN INFORMATION" at 12382.02,6356.17 h60
  text "MIN. TRACK WIDTH:" at 11737.46,6224.05 h60
  text "MIL" at 12988.46,6224.05 h60
  text "10" at 12802,6223 h60
  text "MIL" at 12988.46,6100.91 h60
  text "MIN. CLEARANCE:" at 11737.46,6099.92 h60
  text "6" at 12831,6100 h60
  text "MIN. VIA PAD SIZE:" at 11737.46,5975.8 h60
  text "22" at 12803.71,5975.8 h60
  text "MIL" at 12988.46,5975.8 h60
  text "0.05mm (2MIL)" at 12432.46,5845.9 h60
  text "MINIMUM ANNULAR RING" at 11408.23,5837.67 h60
  text "EXTERNAL" at 13140.46,5837.67 h60
  text "PCB TO BE FABRICATED TO IPC 6012 class 2" at 11410,5724 h60
  text "MIL, HOLES" at 13316.46,5627.07 h60
  text "+/-" at 12924,5618.48 h60
  text "+/-" at 13778,5618.48 h60
  text "REGISTRATION TOLERANCES:" at 11408.23,5617.42 h60
  text "METAL" at 12608,5617.42 h60
  text "5" at 13184.2,5617.42 h60
  text "3" at 14017.2,5617.42 h60
  text "MIL" at 14133.46,5617.42 h60
  text "HOLE SIZE TOLERANCE (UNLESS OTHERWISE SPECIFIED):" at 11408.23,5519.1 h60
  text "+/-" at 13778,5516.23 h60
  text "3" at 14017.2,5515.17 h60
  text "MIL" at 14133.46,5515.17 h60
  text "MATERIAL:" at 11333.46,5377.52 h60
  text "FR-4 High Tg" at 12319.9,5249 h60
  text "X" at 12175.46,5241.01 h60
  text "FR-408" at 11754.46,5236.49 h60
  text "OTHER" at 13242.46,5236.49 h60
  text "62 MIL (1.6mm) +/-10%" at 12074.56,5093.46 h60
  text "X" at 11954.46,5091.01 h60
  text "THICKNESS:" at 11408.23,5085.24 h60
  text "OTHER" at 13359.46,5085.24 h60
  text "TOLERANCE:" at 11408.23,4946.92 h60
  text "X" at 12256.46,4946.92 h60
  text "ANSI IPC-6012 TYPE 3 CLASS 2" at 12434.48,4946.92 h60
  text "OTHER +/-" at 12434.46,4802.73 h60
  text "BOW & TWIST:" at 11408.23,4657.54 h60
  text "X" at 12256.46,4657.54 h60
  text "ANSI IPC-6012 TYPE 3 CLASS 2" at 12434.48,4657.54 h60
  text "OTHER +/-" at 12434.46,4510.85 h60
  text "DRILLING:" at 11333.46,4380.23 h60
  text "NC_DRILL FILES" at 13094.46,4275.04 h60
  text "REFERENCE:" at 11408.23,4271.1 h60
  text "X" at 12065.46,4271.01 h60
  text "AS SHOWN" at 12243.46,4271.1 h60
  text "X" at 12966.46,4271.1 h60
  text "OTHER" at 13392.46,4128.85 h60
  text "PTH COPPER THICKNESS:" at 11407.91,4125.32 h60
  text "X" at 12547.14,4125.32 h60
  text "20-30 um" at 12675.14,4125.32 h60
  text "BOARD FINISH:" at 11333.46,3977.73 h60
  text "SILKSCREEN:" at 11488.68,3867.6 h60
  text "X" at 12446.46,3867.6 h60
  text "TOP" at 12563.46,3867.6 h60
  text "X" at 12956.46,3867.6 h60
  text "BOTTOM" at 13074.46,3867.6 h60
  text "SILKSCREEN COLOR:" at 11488.68,3712.41 h60
  text "X" at 12445.46,3712.41 h60
  text "WHITE" at 12563.46,3712.41 h60
  text "OTHER" at 13074.46,3712.41 h60
  text "X" at 12576.46,3568.96 h60
  text "GREEN" at 12694.46,3568.96 h60
  text "OTHER" at 13312.46,3568.96 h60
  text "SOLDER RESIST COLOR:" at 11488.68,3562.1 h60
  text "MATTE" at 12694.46,3414.71 h60
  text "SEMI-GLOSS" at 13312,3414.07 h60
  text "X" at 13170,3410 h60
  text "IMMERSION GOLD (ENIG)" at 12394.46,3241.94 h60
  text "ENEPIG" at 13732,3234.72 h60
  text "SURFACE FINISH:" at 11333.46,3233.72 h60
  text "X" at 12216.46,3233.72 h60
  text "IMM. TIN/SILVER OR EQUIV" at 11663,3096.4 h60
  text "OTHER" at 13094.46,3092.47 h60
  text "ARRAY/PANEL:" at 11333.46,2937.09 h60
  text "X" at 12209,2929 h60
  text "CUT AND TRIM PER M1 BOARD OUTLINE" at 12394.46,2928.87 h60
  text "N.C. ROUTE" at 12394.46,2792.9 h60
  text "V. SCORE" at 13260.46,2792.9 h60
  text "CERTIFICATION:" at 11333.46,2663.77 h60
  text "MATERIALS AND WORKMANSHIP FOR ALL PCBS" at 12058.46,2663.77 h60
  text "TO MEET OR EXCEED THE REQUIREMENTS OF:" at 12058.46,2569.71 h60
  text "X" at 11695.97,2441.08 h60
  text "ANSI IPC-A-600F CLASS ->" at 11823.96,2441.08 h60
  text "X" at 13471.97,2441.08 h60
  text "2" at 13581.96,2441.08 h60
  text "1" at 13266.96,2439.58 h60
  text "3" at 13935.96,2439.58 h60
  text "X" at 12507.97,2293.39 h60
  text "RoHS" at 12635.96,2293.39 h60
  text "OTHER" at 13280.36,2293.39 h60
  text "PER ORDER" at 13677.42,2293.39 h60
  text "ALL BOARDS MUST MEET OR EXCEED UL94-V0 REQUIREMENTS." at 11361,2139.57 h60
  text "PCB MUST BEAR THE UL94V-0 UL REGISTERED MATERIAL ID NUMBER" at 11361,2023.5 h60
  text "ADDITIONAL REQUIREMENTS:" at 11359,1863 h60
  text "MICROSECTION:" at 11408.23,1746.95 h60
  text "YES" at 12313.96,1746.95 h60
  text "REQUIRED" at 13175.46,1602.62 h60
  text "BARE BOARD ELEC. TEST:" at 11408.23,1599.76 h60
  text "NONE" at 12713.96,1599.76 h60
  text "X" at 13057.46,1599.76 h60
  text "PER ORDER" at 13767.46,1599.76 h60
  text "X" at 11462.97,1447.08 h60
  text "7.874 MIL VIAS REQUIRE NON-CONDUCTIVE FILL AND PLANARIZE" at 11498,1394 h59
  text "XX MIL VIAS REQUIRE CONDUCTIVE FILL AND PLANARIZE" at 11584.38,1290.84 h60
  text "OUTER XX MIL TRACES REQUIRE 50 OHM SINGLE-ENDED IMPEDANCE" at 11583.39,1127.46 h58
  text "LAYER 2 & 3 (INNER LAYERS) XX MIL WIDE, XX MIL SPACE / TRACES REQUIRE 100 OHM DIFFERENTIAL IMPEDANCE" at 11575.39,891.74 h60
  text ".Layer_Name" at 577,-858.49 h60
M11 Gerber Information:
  lines w10: -292,-930.17 6308,-930.17 ; -292,-726.83 6310,-726.83 ; -292,-523.5 -292,-1133.5 3713,-1133.5 6310,-1133.5 6310,-523.5 -291.5,-523.5 -291.5,-1133.5 1284,-1133.5 ; 2173,-1133.5 2173,-523.5 ; 3440,-726.83 3440,-523.5 ; 4280,-726.83 4280,-523.5 ; 4902,-1140 4902,-937.17
  text "ALL ARTWORK VIEWED FROM TOP SIDE" at -228.5,-655.67 h60
  text "BOARD #:" at 2248,-655.67 h60
  text ".PRJ_Number" at 2793.5,-655.67 h60
  text "REV:" at 3638,-655.67 h60
  text ".PCB_Rev" at 3929.5,-655.67 h60
  text "SVN REV:" at 4476,-655.67 h60
  text ".VersionControl_RevNumber" at 4982,-655.67 h60
  text "LAYER NAME =" at -228.5,-858.49 h60
  text "TID #:" at 2248,-859 h60
  text ".TID" at 2793.5,-859 h60
  text "PLOT NAME =" at -228.5,-1064.34 h60
  text ".plot_File_Name" at 577,-1064.34 h60
  text "GENERATED    :" at 2250,-1064.34 h60
  text ".Print_Date" at 3119.5,-1064.34 h60
  text ".Print_Time" at 3848.5,-1064.34 h60
  text "TEXAS INSTRUMENTS" at 5113,-1064.34 h60
M12 Stackup:
  drawing of 715 lines, arcs and shapes, not listed
  text "FOR REFERENCE ONLY" at 7521,6330 h80
  text "Layer" at 5449.2,6150 h60
  text "Name" at 5859.11,6150 h60
  text "Material" at 6788.85,6150 h60
  text "Thickness" at 7648.62,6150 h60
  text "Constant" at 8298.46,6150 h60
  text "Board Layer Stack" at 8868.32,6150 h60
  text "Board Layer Stack" at 9988,6150 h60
  text "1" at 5449.2,6030 h60
  text "Top Overlay" at 5859.11,6030 h60
  text "2" at 5449.2,5910 h60
  text "Top Solder" at 5859.11,5910 h60
  text "Solder Resist" at 6788.85,5910 h60
  text "0.40mil" at 7648.62,5910 h60
  text "3.5" at 8298.46,5910 h60
  text "3" at 5449.2,5790 h60
  text "Top Layer" at 5859.11,5790 h60
  text "Copper" at 6788.85,5790 h60
  text "2.00mil" at 7648.62,5790 h60
  text "4" at 5449.2,5670 h60
  text "Dielectric1" at 5859.11,5670 h60
  text "FR-4" at 6788.85,5670 h60
  text "5.00mil" at 7648.62,5670 h60
  text "4.2" at 8298.46,5670 h60
  text "5" at 5449.2,5550 h60
  text "Mid-Layer 1" at 5859.11,5550 h60
  text "Copper" at 6788.85,5550 h60
  text "2.80mil" at 7648.62,5550 h60
  text "6" at 5449.2,5430 h60
  text "Dielectric2" at 5859.11,5430 h60
  text "FR-4" at 6788.85,5430 h60
  text "12.00mil" at 7648.62,5430 h60
  text "4.2" at 8298.46,5430 h60
  text "7" at 5449.2,5310 h60
  text "Mid-Layer 2" at 5859.11,5310 h60
  text "Copper" at 6788.85,5310 h60
  text "2.80mil" at 7648.62,5310 h60
  text "8" at 5449.2,5190 h60
  text "Dielectric3" at 5859.11,5190 h60
  text "FR-4" at 6788.85,5190 h60
  text "12.00mil" at 7648.62,5190 h60
  text "4.2" at 8298.46,5190 h60
  text "9" at 5449.2,5070 h60
  text "Mid-Layer 3" at 5859.11,5070 h60
  text "Copper" at 6788.85,5070 h60
  text "2.80mil" at 7648.62,5070 h60
  text "10" at 5449.2,4950 h60
  text "Dielectric4" at 5859.11,4950 h60
  text "FR-4" at 6788.85,4950 h60
  text "12.00mil" at 7648.62,4950 h60
  text "4.2" at 8298.46,4950 h60
  text "11" at 5449.2,4830 h60
  text "Mid-Layer 4" at 5859.11,4830 h60
  text "Copper" at 6788.85,4830 h60
  text "2.80mil" at 7648.62,4830 h60
  text "12" at 5449.2,4710 h60
  text "Dielectric5" at 5859.11,4710 h60
  text "FR-4" at 6788.85,4710 h60
  text "5.00mil" at 7648.62,4710 h60
  text "4.2" at 8298.46,4710 h60
  text "13" at 5449.2,4590 h60
  text "Bottom Layer" at 5859.11,4590 h60
  text "Copper" at 6788.85,4590 h60
  text "2.00mil" at 7648.62,4590 h60
  text "14" at 5449.2,4470 h60
  text "Bottom Solder" at 5859.11,4470 h60
  text "Solder Resist" at 6788.85,4470 h60
  text "0.40mil" at 7648.62,4470 h60
  text "3.5" at 8298.46,4470 h60
  text "15" at 5449.2,4350 h60
  text "Bottom Overlay" at 5859.11,4350 h60
  text ".Layer_Name" at 577,-858.49 h60
M13 Component Bodies Top:
  text ".Layer_Name" at 577,-858.49 h60
M14 Component Bodies Bottom:
  text ".Layer_Name" at 577,-858.49 h60
M15 Courtyards Top:
  text ".Layer_Name" at 577,-858.49 h60
M16 Courtyards Bottom:
  text ".Layer_Name" at 577,-858.49 h60
Drill Drawing:
  circle w10: c5539.44,3628.41 r48.28
  lines w15: 5405.95,2211.26 11101.98,2211.26 ; 5405.95,3732.22 11101.98,3732.22 ; 5996.45,1993.98 5996.45,3949.5 ; 6576.7,1993.98 6576.7,3949.5 ; 7689.25,1993.98 7689.25,3949.5 ; 8142.16,1993.98 8142.16,3949.5 ; 8797.84,1993.98 8797.84,3949.5 ; 10063.79,1993.98 10063.79,3949.5 ; 5405.95,1993.98 11101.98,1993.98 11101.98,3949.5 5405.95,3949.5 5405.95,1993.98
  text "Symbol" at 5536.32,3797.4 h125.73
  text "Quantity" at 6061.63,3797.4 h125.73
  text "Finished Hole Size" at 6641.88,3797.4 h125.73
  text "Plated" at 7754.43,3797.4 h125.73
  text "Hole Type" at 8207.35,3797.4 h125.73
  text "Drill Layer Pair" at 8863.03,3797.4 h125.73
  text "Hole Tolerance" at 10128.98,3797.4 h125.73
  text "166" at 6061.63,3580.12 h104.77
  text "7.800mil (0.198mm)" at 6641.88,3580.12 h104.77
  text "PTH" at 7754.43,3580.12 h104.77
  text "Round" at 8207.35,3580.12 h104.77
  text "Top Layer - Bottom Layer" at 8863.03,3580.12 h104.77
  text "+3.000mil/-7.874mil" at 10128.98,3580.12 h104.77
  text "24" at 6061.63,3362.84 h104.77
  text "7.874mil (0.200mm)" at 6641.88,3362.84 h104.77
  text "PTH" at 7754.43,3362.84 h104.77
  text "Round" at 8207.35,3362.84 h104.77
  text "Top Layer - Bottom Layer" at 8863.03,3362.84 h104.77
  text "A" at 5497.26,3352.86 h96.57
  text "6" at 6061.63,3145.56 h104.77
  text "29.528mil (0.750mm)" at 6641.88,3145.56 h104.77
  text "PTH" at 7754.43,3145.56 h104.77
  text "Round" at 8207.35,3145.56 h104.77
  text "Top Layer - Bottom Layer" at 8863.03,3145.56 h104.77
  text "B" at 5497.26,3135.58 h96.57
  text "61" at 6061.63,2928.28 h104.77
  text "40.000mil (1.016mm)" at 6641.88,2928.28 h104.77
  text "PTH" at 7754.43,2928.28 h104.77
  text "Round" at 8207.35,2928.28 h104.77
  text "Top Layer - Bottom Layer" at 8863.03,2928.28 h104.77
  text "C" at 5497.26,2918.3 h96.57
  text "12" at 6061.63,2711 h104.77
  text "49.213mil (1.250mm)" at 6641.88,2711 h104.77
  text "PTH" at 7754.43,2711 h104.77
  text "Round" at 8207.35,2711 h104.77
  text "Top Layer - Bottom Layer" at 8863.03,2711 h104.77
  text "D" at 5497.26,2701.02 h96.57
  text "15" at 6061.63,2493.72 h104.77
  text "63.000mil (1.600mm)" at 6641.88,2493.72 h104.77
  text "PTH" at 7754.43,2493.72 h104.77
  text "Round" at 8207.35,2493.72 h104.77
  text "Top Layer - Bottom Layer" at 8863.03,2493.72 h104.77
  text "E" at 5497.26,2483.74 h96.57
  text "4" at 6061.63,2276.44 h104.77
  text "126.000mil (3.200mm)" at 6641.88,2276.44 h104.77
  text "NPTH" at 7754.43,2276.44 h104.77
  text "Round" at 8207.35,2276.44 h104.77
  text "Top Layer - Bottom Layer" at 8863.03,2276.44 h104.77
  text "F" at 5497.26,2266.46 h96.57
  text "288 Total" at 6061.63,2059.16 h104.77
  text ".Layer_Name" at 577,-858.49 h60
